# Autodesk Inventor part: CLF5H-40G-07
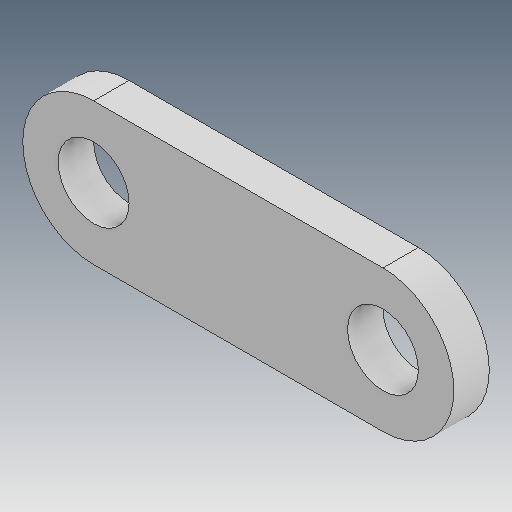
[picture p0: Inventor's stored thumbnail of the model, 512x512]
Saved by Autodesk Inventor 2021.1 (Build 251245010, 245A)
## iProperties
Created: 2013-04
Part Number: CLF5H-40G-07
Material: Ogólny
Document SubType Name: Modeling
Designer: user
Density: 1 g/cm^3
Appearance: Domyślna
Author: user
Revision Number: ÈÎºÎ
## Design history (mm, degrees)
feature "Í¹Ì¨-À­Éì1"
node "Bryła1"
